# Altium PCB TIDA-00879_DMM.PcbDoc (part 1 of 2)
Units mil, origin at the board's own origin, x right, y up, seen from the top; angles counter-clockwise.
Board outline 2700 x 5000 mil, 4 copper layers (Layer 1 - Top Layer, Layer 2 - GND, Layer 3 - PWR, Layer 4 - Bottom Layer), stack 61.434 mil thick; 140 components, 132 nets, 483 pads, 130 vias.
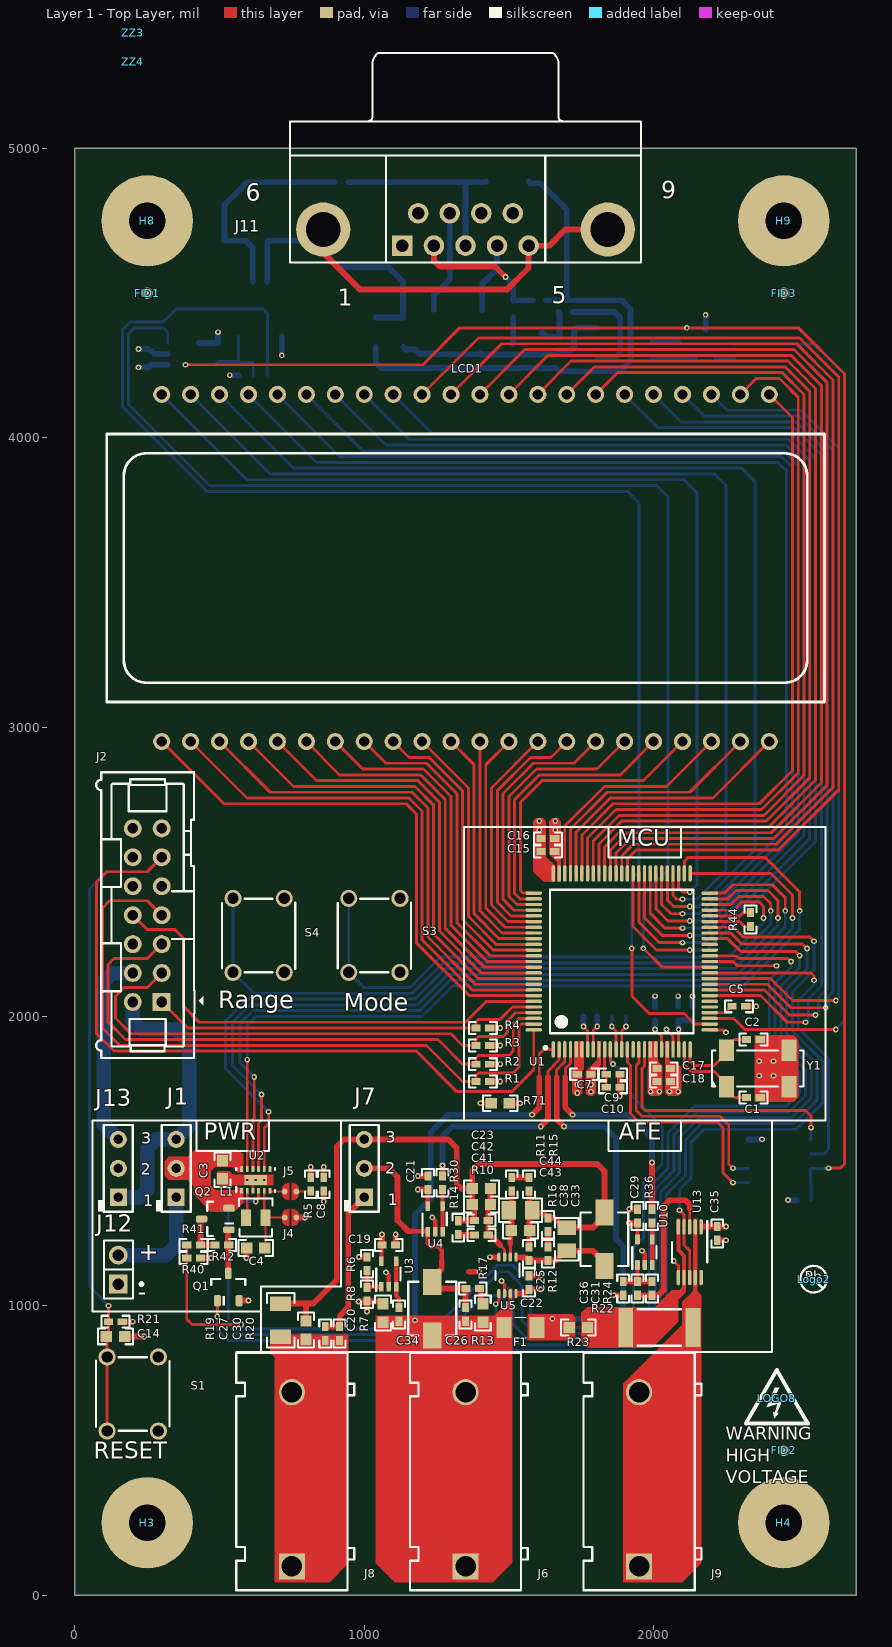
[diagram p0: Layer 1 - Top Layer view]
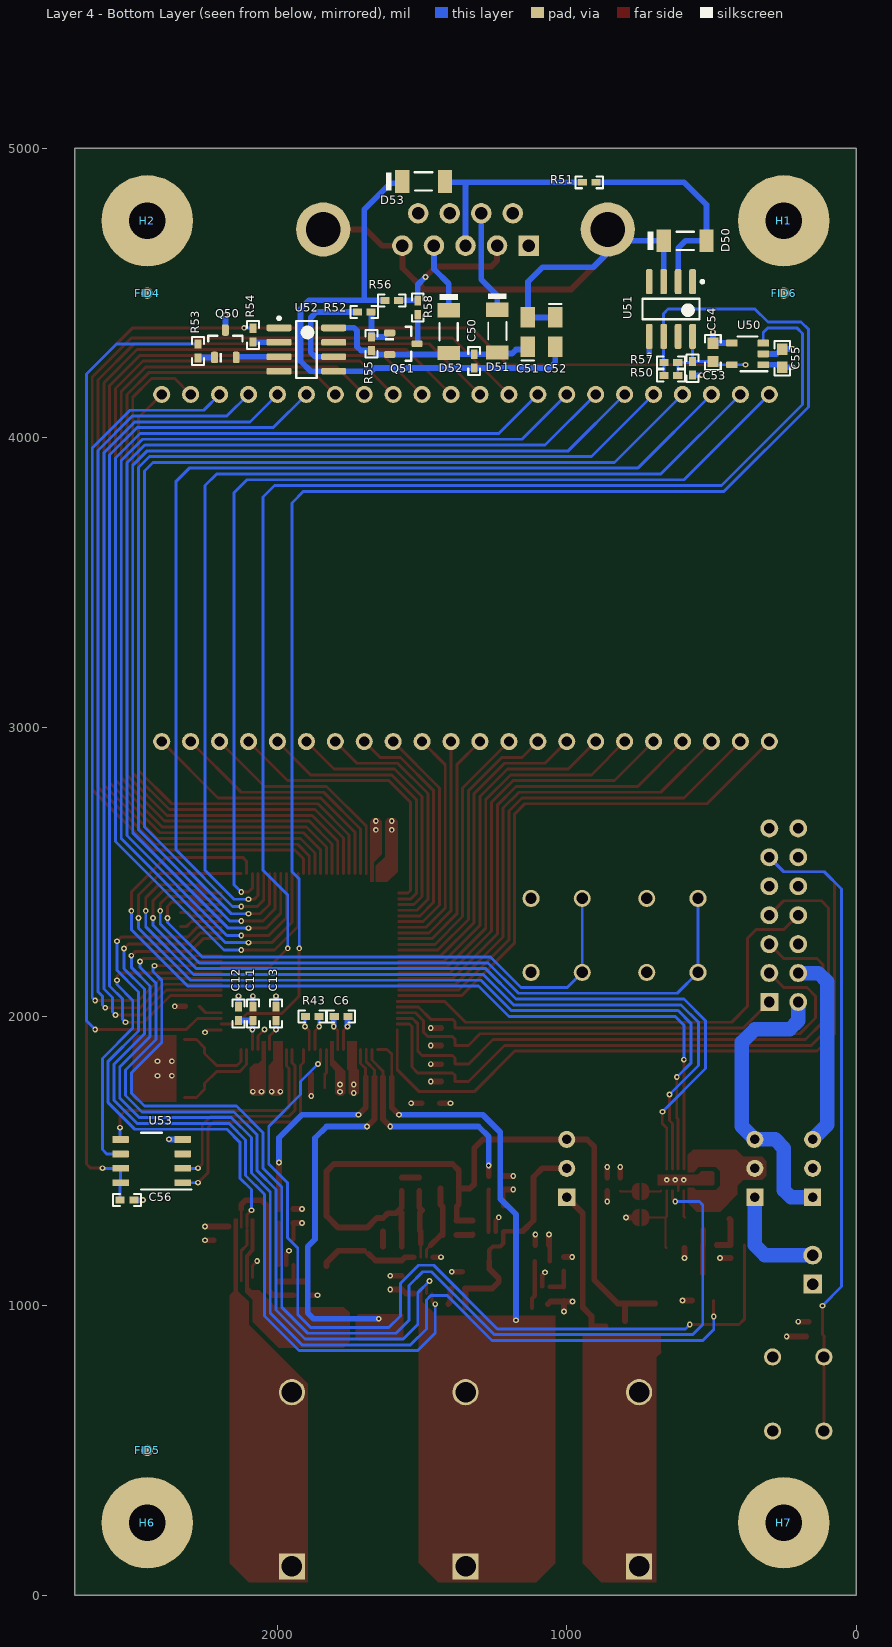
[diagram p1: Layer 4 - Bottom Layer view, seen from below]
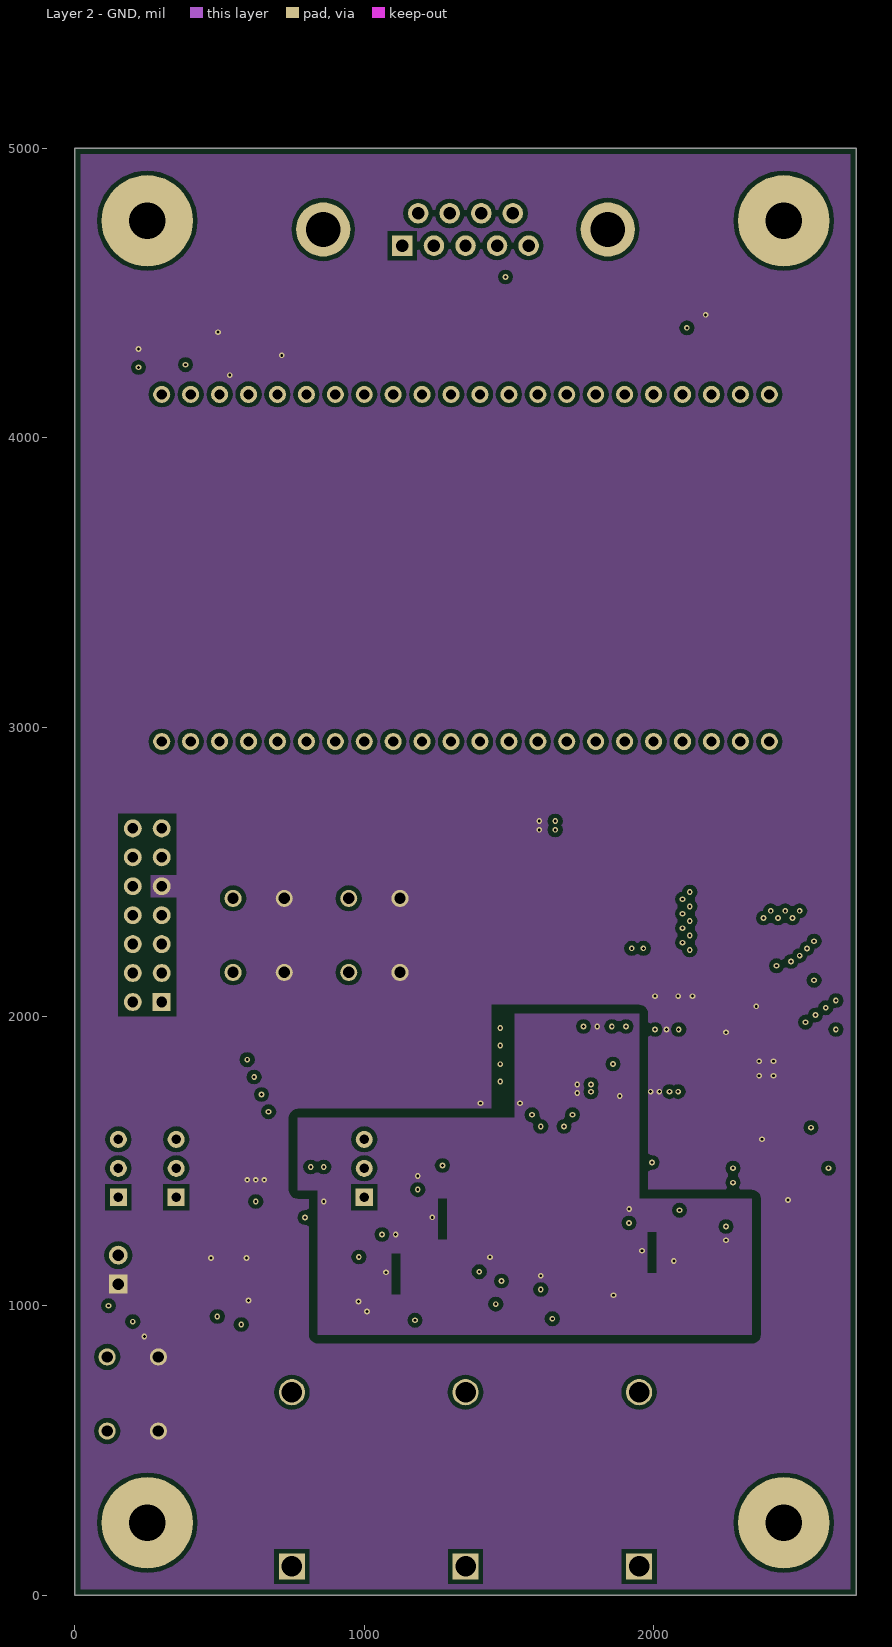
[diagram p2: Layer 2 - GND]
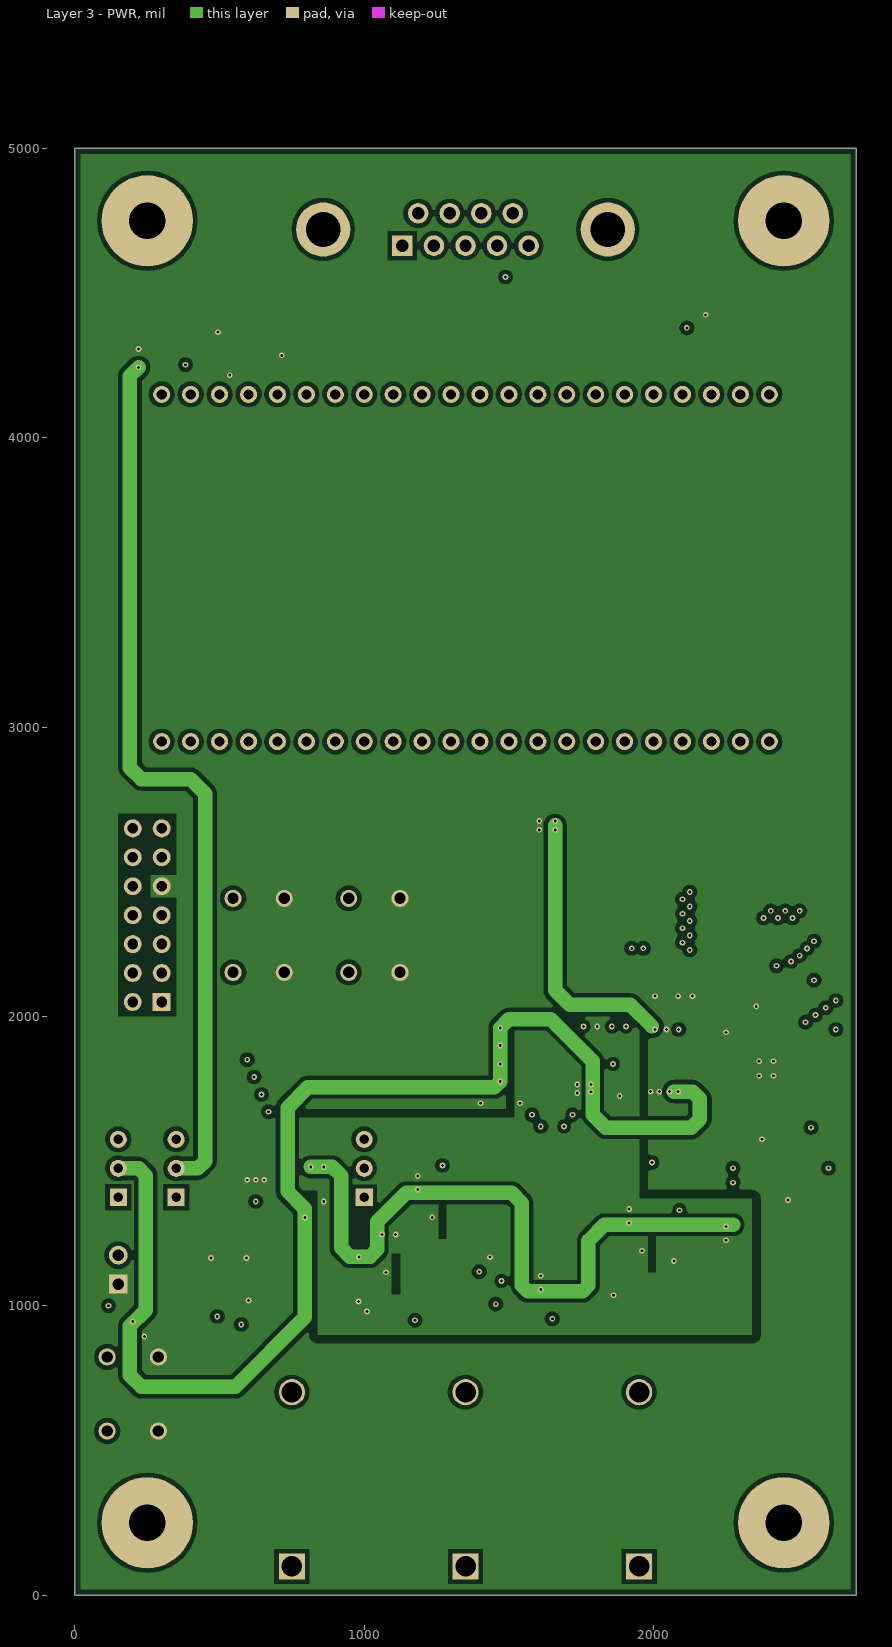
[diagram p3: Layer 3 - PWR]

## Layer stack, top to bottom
Top Solder: solder mask 0.4, Solder Resist, Dk 3.5
Layer 1 - Top Layer: signal copper 1.4
Dielectric 1: prepreg 18.6, 370HR, Dk 4.2
Layer 2 - GND: signal copper 1.417
Dielectric 2: core 18.6, 370HR, Dk 4.2
Layer 3 - PWR: signal copper 1.417
Dielectric 3: prepreg 18.6, 370HR, Dk 4.2
Layer 4 - Bottom Layer: signal copper 1.4
Bottom Solder: solder mask 0.4, Solder Resist, Dk 3.5

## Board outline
0,0 0,5000 2700,5000 2700,0

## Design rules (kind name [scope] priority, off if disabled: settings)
AcuteAngle [All] p1: minimum=4.50000000000000E+0001 checktracksonly=FALSE
AssemblyTestPointUsage [All] p1: valid=2
Clearance Clearance_Keepouts [((IsTrack Or IsArc) And Not InPoly) And IsFree and IsKeepOut vs ((IsTrack Or IsArc) And Not InPoly) And IsFree and IsKeepOut] p1: gap=0
Clearance Clearance_Poly [InPolygon] p2: gap=15 except(30: Poly-Poly)
Clearance [All] p3: gap=7
ComponentClearance ComponentClearance_MountingHoles_FiducialMarks [InComponentClass('Mounting Holes') vs InComponentClass('FiducialMark')] p1: gap=50 collisioncheckmode=3 verticalgap=10 showdistances=FALSE
ComponentClearance ComponentClearance_Shunt [InComponentClass('Header') vs InComponentClass('Shunt')] p2: gap=0 collisioncheckmode=3 verticalgap=0 showdistances=FALSE
ComponentClearance ComponentClearance_Logo [InComponentClass('Logo')] p3: gap=20 collisioncheckmode=3 verticalgap=10 showdistances=FALSE
ComponentClearance ComponentClearance_ScrewToNut [(HasFootprint('NY PMS 440 0025 PH')) vs (HasFootprint('Keystone_1902C'))] p4: gap=5 collisioncheckmode=3 verticalgap=10 showdistances=FALSE
ComponentClearance ComponentClearance_MountingHoles [InComponentClass('Mounting Holes')] p5: gap=25 collisioncheckmode=3 verticalgap=100000 showdistances=FALSE
ComponentClearance ComponentClearance_SmallPassives [HasFootprint('0201*') or HasFootprint('0402*') or HasFootprint('0508') or HasFootprint('0603*') or HasFootprint('0612') or HasFootprint('0805*') or HasFootprint('0815*') or HasFootprint('0830*') or HasFootprint('1206*') or HasFootprint('1210*') or HasFootprint('1808*') or HasFootprint('1812*') or HasFootprint('1825*') or HasFootprint('2010*') or HasFootprint('2220*') or HasFootprint('2225*') or HasFootprint('2512*') or HasFootprint('2728*') or HasFootprint('3518*') vs HasFootprint('0201*') or HasFootprint('0402*') or HasFootprint('0508') or HasFootprint('0603*') or HasFootprint('0612') or HasFootprint('0805*') or HasFootprint('0815*') or HasFootprint('0830*') or HasFootprint('1206*') or HasFootprint('1210*') or HasFootprint('1808*') or HasFootprint('1812*') or HasFootprint('1825*') or HasFootprint('2010*') or HasFootprint('2220*') or HasFootprint('2225*') or HasFootprint('2512*') or HasFootprint('2728*') or HasFootprint('3518*')] p6: gap=10 collisioncheckmode=3 verticalgap=10 showdistances=FALSE
ComponentClearance ComponentClearance_THtoSMT [IsThruComponent vs IsSMTComponent] p7: gap=10 collisioncheckmode=3 verticalgap=30 showdistances=FALSE
ComponentClearance ComponentClearance_THtoTH [IsThruComponent vs IsThruComponent] p8: gap=10 collisioncheckmode=3 verticalgap=10 showdistances=FALSE
ComponentClearance [All] p9: gap=10 collisioncheckmode=3 verticalgap=10 showdistances=FALSE
DiffPairsRouting [All] p1: maxlimit=100 minlimit=10 mostfreqgap=10 toplayer_minwidth=15 toplayer_maxwidth=15 toplayer_prefwidth=15 midlayer1_minwidth=15 midlayer1_maxwidth=15 midlayer1_prefwidth=15 midlayer2_minwidth=15 midlayer2_maxwidth=15 midlayer2_prefwidth=15 bottomlayer_minwidth=15 bottomlayer_maxwidth=15 bottomlayer_prefwidth=15 maxuncoupledlength=1000
FabricationTestPointUsage TestPointUsage [All] p1: valid=2 allowmultiple=FALSE
FabricationTestpoint Testpoint [All] p1: side=3 testpointundercomponent=TRUE minsize=40 maxsize=100 preferedsize=60 minholesize=0 maxholesize=40 preferedholesize=32 testpointgrid=1 allowsidetop=TRUE allowsidebottom=TRUE usegrid=TRUE gridtolerance=0.01
FanoutControl Fanout_LCC [IsLCC] p1: bgadir=Out bgaviamode=Centered fanoutstyle=Auto fanoutdirection=Alternating viagrid=1 // Fanout_LCC (Default Rule)
FanoutControl Fanout_BGA [IsBGA] p2: bgadir=Out bgaviamode=Centered fanoutstyle=Auto fanoutdirection=Alternating viagrid=1 // Fanout_BGA (Default Rule)
FanoutControl Fanout_Default [All] p4: bgadir=Out bgaviamode=Centered fanoutstyle=Auto fanoutdirection=Alternating viagrid=1 // Fanout_Default (Default Rule)
FanoutControl Fanout_Small [(CompPinCount < 5)] p5: bgadir=Out bgaviamode=Centered fanoutstyle=Auto fanoutdirection=OutThenIn viagrid=1 // Fanout_Small (Default Rule)
HoleSize [All] p1: absolutevalues=TRUE maxlimit=251 minlimit=7.87 maxpercent=80.000 minpercent=20.000
MinimumAnnularRing MinimumAnnularRing_ThermalPadVias [IsVia and InAnyComponent] p1: minimumring=5.91
MinimumAnnularRing [All] p2: minimumring=5
MinimumSolderMaskSliver MinimumSolderMaskSliver_Logo [InComponentClass('Logo') vs InComponentClass('Logo')] p1: minsoldermaskwidth=0.7
MinimumSolderMaskSliver [All] p2: minsoldermaskwidth=3.94
PlaneConnect [All] p1: planeconnectstyle=Relief reliefexpansion=10 reliefentries=4 reliefconductorwidth=10 reliefairgap=10
PolygonConnect [All] p1: connectstyle=Direct reliefconductorwidth=10 reliefentries=4 polygonreliefangle="90 Angle" airgapwidth=10
RoutingVias ThermalPadVias [IsVia and InAnyComponent] p1: holewidth=7.87 width=19.68 viastyle="Through Hole" minholewidth=7.87 minwidth=19.68 maxholewidth=12.99 maxwidth=23.62
RoutingVias [All] p2: holewidth=16 width=34 viastyle="Through Hole" minholewidth=7.87 minwidth=20 maxholewidth=40 maxwidth=65
SilkToBoardRegionClearance [Not ((IsComment or IsDesignator) And (Hide <> 'False')) and not InRegion(1000,500,4000,800)] p1:
SilkToSilkClearance SilkToSilkClearance_Pb-FreeLogo [(HasFootprint('Pb-Free_Overlay_Medium') OR HasFootprint('Pb-Free_Overlay_Small')) vs (HasFootprint('Pb-Free_Overlay_Medium') OR HasFootprint('Pb-Free_Overlay_Small'))] p1: silktosilkclearance=0
SilkToSilkClearance [All] p2: silktosilkclearance=4
SilkToSolderMaskClearance SilkToComponentPadClearance [IsPad and InAnycomponent] p1: minsilkscreentomaskgap=5 clearancetoexposedcopper=TRUE
SilkToSolderMaskClearance "Silk to Solder Mask Opening" [All] p2: minsilkscreentomaskgap=4 clearancetoexposedcopper=FALSE
SolderMaskExpansion [All] p1: expansion=1.97
Width [All] p1: maxlimit=100 minlimit=6 preferedwidth=10 checkconnectedcopper=TRUE
15 further rules are at their usual default settings.

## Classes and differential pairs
component class TIDA-00879_TEST: C50 C51 C52 C53 C54 C55 C56 D11 D50 D51 D52 D53 J11 Q50 Q51 R50 R51 R52 R53 R54 R55 R56 R57 R58 U50 U51 U52 U53
net class S[39..0]: S0 S1 S2 S3 S4 S5 S6 S7 S8 S9 S10 S11 S12 S13 S14 S15 S16 S17 S18 S19 S20 S21 S22 S23 S24 S25 S26 S27 S28 S29 S30 S31 S32 S33 S34 S35 S36 S37 S38 S39
component class TIDA-00879_MCU: C1 C2 C3 C4 C5 C6 C7 C8 C9 C10 C11 C12 C13 C14 C15 C16 C17 C18 J1 J2 J4 J5 J12 J13 L1 LCD LCD1 Q1 Q2 R1 R2 R3 R4 R5 R21 R40 R41 R42 R43 R44 R71 S1 S3 S4 U1 U2 Y1
component class "Mounting Holes": H3 H4 H8 H9
component class TIDA-00879_AFE: C19 C20 C21 C22 C23 C25 C26 C27 C29 C30 C31 C33 C34 C35 C36 C38 C41 C42 C43 C44 F1 J6 J7 J8 J9 LOGO8 R6 R7 R8 R10 R11 R12 R13 R14 R15 R16 R17 R19 R20 R22 R23 R24 R30 R36 U3 U4 U5 U10 U13
component class TIDA-00879_MISC: FID1 FID2 FID3 FID4 FID5 FID6 H1 H2 H3 H4 H6 H7 H8 H9 Logo2 ZZ2 ZZ3 ZZ4
component class FiducialMark: FID1 FID2 FID3 FID4 FID5 FID6
component class AssemblyNote: ZZ2 ZZ3 ZZ4
component class Header: J1 J2 J7 J12 J13
net class COM[3..0]: COM0 COM1 COM2 COM3

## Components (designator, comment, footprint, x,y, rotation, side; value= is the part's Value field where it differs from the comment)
C1 "GRM1555C1H180JA01D" 0402 2345,1720 r180 top
C2 "GRM1555C1H180JA01D" 0402 2345,1920 r0 top
C3 "GRM188R60J106ME84" 0603 510,1470 r270 top
C4 "GRM188R60J106ME84" 0603 625,1200 r180 top
C5 "C1005X5R1A475K050BC" 0402 2295,2035 r180 top
C6 "C1005X5R1A104K050BA" 0402 1780,2000 r0 bottom
C7 "C1005X5R1A104K050BA" 0402 1760,1800 r180 top
C8 "GRM155R60J226ME11D" 0402 860,1420 r90 top
C9 "C1005X5R1A104K050BA" 0402 1860,1800 r0 top
C10 "C1005X5R1A475K050BC" 0402 1860,1755 r180 top
C11 "C1005X5R1A104K050BA" 0402 2085,2010 r90 bottom
C12 "C1005X5R1A475K050BC" 0402 2135,2010 r90 bottom
C13 "C1005X5R1A104K050BA" 0402 2005,2010 r90 bottom
C14 "06033C104JAT2A" 0603 140.45,894.19 r0 top
C15 "C1005X5R1A104K050BA" 0402 1635,2570 r180 top
C16 "C1005X5R1A475K050BC" 0402 1635,2615 r0 top
C17 "C1005X5R1A104K050BA" 0402 2035,1820 r180 top
C18 "C1005X5R1A475K050BC" 0402 2035,1775 r0 top
C19 "C1005X5R1A104K050BA" 0402 1085,1210 r0 top
C20 "Used in BOM report" 0603 1065,975 r90 top
C21 "C1005X5R1A104K050BA" 0402 1220,1425 r90 top
C22 "C1005X5R1A104K050BA" 0402 1570,1080 r90 top
C23 "C0603C104J4RACTU" 0603 1405,1405 r0 top
C25 "GRM1555C1H511GA01D" 0402 1570,1180 r270 top
C26 "Used in BOM report" 0402 1350,970 r270 top
C27 "C1608C0G2A101F080AA" 0603 799,916 r90 top
C29 "C1005X5R1A104K050BA" 0402 1945,1310 r90 top
C30 "GRM1555C1H101FA01D" 0402 865,904.02 r90 top
C31 "Used in BOM report" 0402 1945,1060 r90 top
C33 "TZB4R200AB10B00" Murata_TZB4_A 1830,1230 r270 top
C34 "TZB4R200AB10B00" Murata_TZB4_A 1235,990 r270 top
C35 "C1005X5R1A104K050BA" 0402 2220,1250 r270 top
C36 "Used in BOM report" 0402 1895,1060 r90 top
C38 "08055A471FAT2A" 0805_HV 1700,1230 r270 top
C41 "GRM1557U1A182JA01D" 0402 1405,1295 r0 top
C42 "C1608C0G1E822J" 0603 1405,1350 r0 top
C43 "C0603C911J5GACTU" 0603 1540,1260 r180 top
C44 "C0805C103F1GACTU" 0805_HV 1540,1330 r180 top
C50 "C1005X5R1A104K050BA" 0402 1320,4265 r90 bottom
C51 "293D106X9050E2TE3" 3216-18 1135,4365 r90 bottom
C52 "293D106X9050E2TE3" 3216-18 1040,4365 r270 bottom
C53 "C1005X5R1A104K050BA" 0402 565,4240 r270 bottom
C54 "GRM188R61A105KA61D" 0603 495,4295 r90 bottom
C55 "GRM188R61A105KA61D" 0603 255,4275 r90 bottom
C56 "C1005X5R1A104K050BA" 0402 2520,1365 r180 bottom
D50 "LL103A-GS08" SOD-80 591,4681 r180 bottom
D51 "LL103A-GS08" SOD-80 1240,4369 r270 bottom
D52 "LL103A-GS08" SOD-80 1408,4367 r270 bottom
D53 "LL103A-GS08" SOD-80 1495,4886 r180 bottom
F1 "NANOSMDC020F-2" FUSE_NANO02 1540,925 r0 top
FID1 "Fiducial" Fiducial10-30#1 250,4500 r0 top
FID2 "Fiducial" Fiducial10-30#1 2450,500 r90 top
FID3 "Fiducial" Fiducial10-30#2 2450,4650 r0 top
FID4 "Fiducial" Fiducial10-30#1 2450,4500 r90 bottom
FID5 "Fiducial" Fiducial10-30#1 2450,500 r90 bottom
FID6 "Fiducial" Fiducial10-30#1 250,4500 r90 bottom
H1 "1902C" Keystone_1902C 250,4750 r180 bottom locked
H2 "1902C" Keystone_1902C 2450,4750 r180 bottom locked
H3 "NY PMS 440 0025 PH" "NY PMS 440 0025 PH" 250,250 r0 top locked
H4 "NY PMS 440 0025 PH" "NY PMS 440 0025 PH" 2450,250 r0 top locked
H6 "1902C" Keystone_1902C 2450,250 r180 bottom locked
H7 "1902C" Keystone_1902C 250,250 r180 bottom locked
H8 "NY PMS 440 0025 PH" "NY PMS 440 0025 PH" 250,4750 r0 top locked
H9 "NY PMS 440 0025 PH" "NY PMS 440 0025 PH" 2450,4750 r0 top locked
J1 "800-10-003-10-001000" Mill-Max_800-10-003-10-001000 350,1475 r90 top
J2 "N2514-6002-RB" 3M_x2514-60xx 250,2350 r90 top
J4 "Used in BOM report" JUMPER_SPCL 745,1305 r270 top
J5 "Used in BOM report" JUMPER_SPCL 745,1395 r270 top
J6 "571-0500" 571-0500 1350,400 r90 top
J7 "800-10-003-10-001000" Mill-Max_800-10-003-10-001000 1000,1475 r90 top
J8 "571-0100" 571-0100 750,400 r90 top
J9 "571-0200" 571-0200 1950,400 r90 top
J11 "182-009-213R171" NORCOMP_182-009-213R171 1350,5094 r0 top locked
J12 "90120-0122" CONN_90120-0122 150,1125 r90 top
J13 "800-10-003-10-001000" Mill-Max_800-10-003-10-001000 150,1475 r90 top
L1 "VLF302515MT-2R2M" VLF302515MT 625,1305 r0 top
LCD1 "FH-1152P" FH-1152P 1350,3550 r0 top locked
Logo2 "Pb-Free Symbol" Pb-Free_Overlay_Small 2553,1092 r0 top
LOGO8 "WARNING HIGH VOLTAGE" IEC_HighVoltage_Small 2426,681 r0 top
Q1 "BSS138" SOT-23 530,1065 r90 top
Q2 "FDN302P" SOT-23 485,1300 r180 top
Q50 "BC857B" SOT-23 2180,4325 r90 bottom
Q51 "BC857B" SOT-23 1565,4325 r180 bottom
R1 "CRCW040210K0JNED" 0402 1410,1775 r0 top
R2 "CRCW040210K0JNED" 0402 1410,1835 r0 top
R3 "CRCW040210K0JNED" 0402 1410,1900 r0 top
R4 "CRCW040210K0JNED" 0402 1410,1960 r0 top
R5 "CRCW040210R0JNED" 0402 815,1420 r90 top
R6 "CRCW0402100KFKED" 0402 1010,1145 r90 top
R7 "CRCW04024R70JNED" 0402 1120,970 r90 top
R8 "CRCW0402100KFKED" 0402 1010,1040 r90 top
R10 "CRCW04029K09FKED" 0402 1405,1245 r0 top
R11 "CRCW040290K9FKED" 0402 1510,1420 r270 top
R12 "CRCW04021M00FKED" 0402 1635,1180 r270 top
R13 "CRCW0603100MJPEAHR" 0603 1410,975 r270 top
R14 "CRCW040210R0FKED" 0402 1325,1270 r270 top
R15 "CRCW0402931RFKED" 0402 1570,1420 r90 top
R16 "CRCW040210K2FKED" 0402 1635,1280 r270 top
R17 "CRCW04020000Z0ED" 0402 1375,1060 r0 top
R19 "CRHV1206AF10M0FKE5" 1206 711,950 r90 top
R20 "CRCW0402499KFKED" 0402 915,904.02 r90 top
R21 "CRCW040247K0JNED" 0402 140,945 r0 top
R22 "CRCW251295R3FKEG" 2512 2020,925 r180 top
R23 "RL0603FR-070R5L" 0603 1740,925 r180 top
R24 "CRCW04020000Z0ED" 0402 1995,1060 r270 top
R30 "CRCW0402100RFKED" 0402 1270,1425 r270 top
R36 "CRCW0402100RFKED" 0402 1995,1310 r270 top
R40 "CRCW0402100KFKED" 0402 410,1165 r180 top
R41 "CRCW0402249KFKED" 0402 410,1210 r0 top
R42 "CRCW04021M00JNED" 0402 508,1210 r180 top
R43 "Used in BOM report" 0402 1880,2000 r180 bottom
R44 "Used in BOM report" 0402 2335,2335 r270 top
R50 "CRCW04022K20FKED" 0402 640,4215 r0 bottom
R51 "CRCW04021K00JNED" 0402 922,4883 r0 bottom
R52 "CRCW04021K00JNED" 0402 1700,4435 r180 bottom
R53 "CRCW04022K20JNED" 0402 2275,4300 r270 bottom
R54 "CRCW040268R0JNED" 0402 2085,4355 r270 bottom
R55 "CRCW040210K0JNED" 0402 1675,4325 r270 bottom
R56 "CRCW04021K50JNED" 0402 1605,4475 r180 bottom
R57 "CRCW04022K20FKED" 0402 640,4260 r180 bottom
R58 "CRCW0402220RJNED" 0402 1515,4450 r270 bottom
R71 "CRCW06030000Z0EA" 0603 1470,1700 r180 top
S1 "EVQ-PAD04M" SW_EVQ-PAD04M 200,695 r0 top
S3 "EVQ-PAD04M" SW_EVQ-PAD04M 1035,2280 r180 top
S4 "EVQ-PAD04M" SW_EVQ-PAD04M 635,2280 r180 top
U1 "MSP430F6736IPZ" PZ0100A_N 1890,2190 r90 top locked
U2 "TPS62740DSSR" DSS0012A 625,1435 r90 top
U3 "OPA333AIDCKT" DCK0005A_N 1085,1110 r90 top
U4 "OPA333AIDCKT" DCK0005A_N 1245,1300 r90 top
U5 "TS5A3359DCUR" DCU0008A_N 1495,1105 r270 top
U10 "OPA333AIDCKT" DCK0005A_N 1970,1185 r90 top
U13 "TS3A24159DGSR" DGS0010A_N 2125,1185 r270 top
U50 "TPS78230DDCR" DDC0005A_N 375,4290 r0 bottom
U51 "PS8802-1" SO-8 640,4445 r270 bottom
U52 "PS8802-1" SO-8 1900,4305 r180 bottom
U53 "23K640-I/SN" SOIC-8 2435,1500 r0 bottom
Y1 "MC-306 32.768K-E3:ROHS" XTAL_MC-306 2360,1820 r90 top
ZZ2 "These assemblies are ESD sensitive, ESD precautions shall be observed." AssemblyNote 200,5500 r0 top
ZZ3 "These assemblies must be clean and free from flux and all contaminants. Use of no clean flux is not acceptable." AssemblyNote 200,5400 r0 top
ZZ4 "These assemblies must comply with workmanship standards IPC-A-610 Class 2, unless otherwise specified." AssemblyNote 200,5300 r0 top

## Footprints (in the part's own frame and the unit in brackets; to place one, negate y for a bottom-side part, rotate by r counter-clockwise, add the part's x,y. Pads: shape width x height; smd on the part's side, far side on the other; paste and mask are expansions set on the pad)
3M_x2514-60xx [mil] "3M"
  rect 62x62 hole 37 paste+2: 1(-300,-50)
  round 62 hole 37: 2(-300,50) 3(-200,-50) 4(-200,50) 5(-100,-50) 6(-100,50) 7(0,-50) 8(0,50) 9(100,-50) 10(100,50) 11(200,-50) 12(200,50) 13(300,-50) 14(300,50)
  silkscreen extent -494,-193 494,177, body extent -494,-161 494,179, height 390
0402 [mm] "0402 from SM-752 data"
  rect 0.8x0.6 smd: 1(-0.6,0) 2(0.6,0)
  silkscreen extent -1.22,-0.52 1.22,0.52, body extent -0.55,-0.3 0.55,0.3, height 0.6
571-0100 [mm] "Deltron Emcon recommended land pattern 2003-10-13"
  rect 2.3x2.3 hole 1.8: 1(-7.65,0)
  round 2.3 hole 1.8: 2(7.65,0)
  silkscreen extent -9.74,-5.47 11.09,4.88, body extent -12.28,-5.48 11.09,4.88, height 12.41
571-0200 [mm] "Deltron Emcon recommended land pattern 2003-10-13"
  rect 2.3x2.3 hole 1.8: 1(-7.65,0)
  round 2.3 hole 1.8: 2(7.65,0)
  silkscreen extent -9.74,-5.47 11.09,4.88, body extent -12.28,-5.48 11.09,4.88, height 12.41
571-0500 [mm] "Deltron Emcon recommended land pattern 2003-10-13"
  rect 2.3x2.3 hole 1.8: 1(-7.65,0)
  round 2.3 hole 1.8: 2(7.65,0)
  silkscreen extent -9.74,-5.47 11.09,4.88, body extent -12.28,-5.48 11.09,4.88, height 12.41
0603 [mm] "0603 from SM-752 data"
  rect 1x0.95 smd: 1(-0.8,0) 2(0.8,0)
  silkscreen extent -1.52,-0.69 1.52,0.69, body extent -0.87,-0.47 0.87,0.47, height 1
0805_HV [mil] "0805 with 30mil clearance between pads"
  rect 50x63 smd: 1(-40,0) 2(40,0)
  silkscreen extent -74,-40 74,40, body extent -43,-29 43,29, height 57
1206 [mm] "1206 from SM-752 data"
  rect 1.3x1.85 smd: 1(-1.45,0) 2(1.45,0)
  silkscreen extent -2.4,-1.21 2.4,1.21, body extent -1.7,-0.9 1.7,0.9, height 1.35
2512 [mm] "Chip Resistor, Body 6.3x3.2mm, IPC Medium Density"
  rect 1.3x3.4 smd: 1(-2.95,0) 2(2.95,0)
  silkscreen extent -1.9,-1.6 1.9,1.6, body extent -3.22,-1.67 3.22,1.67, height 0.71
3216-18 [mm] "Medium density IPC, based on Kemet T495 dimensions"
  rect 1.8x1.25 smd: 1(-1.3,0) 2(1.3,0)
  silkscreen extent -2.49,-0.54 -2.49,0.54, body extent -1.7,-0.9 1.7,0.9, height 1.8
AssemblyNote [mil] "Assembly Note"
CONN_90120-0122 [mm] "Molex"
  rect 1.65x1.65 hole 1.016 mask+0: 1(-1.27,0)
  round 1.65 hole 1.016 mask+0: 2(1.27,0)
  silkscreen extent -2.54,-2.16 2.54,1.27, body extent -2.54,-1.27 2.54,1.27, height 9.29
DCK0005A_N [mm] "SOT353, 5-Leads, Body 2x1.3mm, Pitch 0.65mm, Lead Span 2.1mm, IPC Medium Density"
  rrect25% 0.85x0.4 smd: 1(-1.125,0.65) 2(-1.125,0) 3(-1.125,-0.65) 4(1.125,-0.65) 5(1.125,0.65)
  silkscreen extent -1.48,-1.02 0.55,1.1, body extent -1.14,-1 1.14,1, height 0.95
DCU0008A_N [mm] "TSSOP, 8-Leads, Body 2x2.3mm, Pitch 0.5mm, IPC Medium Density"
  oval 0.8x0.3 smd: 1(-1.6,0.75) 2(-1.6,0.25) 3(-1.6,-0.25) 4(-1.6,-0.75) 5(1.6,-0.75) 6(1.6,-0.25) 7(1.6,0.25) 8(1.6,0.75)
  silkscreen extent -1.05,-1.05 0.38,1.05, body extent -1.56,-1 1.56,1, height 0.9
DDC0005A_N [mm]
  rrect17% 1x0.6 smd: 1(-1.375,0.95) 2(-1.375,0) 3(-1.375,-0.95) 4(1.375,-0.95) 5(1.375,0.95)
  silkscreen extent -1.75,-1.52 0.88,1.53, body extent -1.41,-1.45 1.41,1.45, height 1.1
DGS0010A_N [mm] "TSSOP, 10-Leads, Body 3x3mm, Pitch 0.5mm, IPC Medium Density"
  oval 1.35x0.3 smd: 1(-2.225,1) 2(-2.225,0.5) 3(-2.225,0) 4(-2.225,-0.5) 5(-2.225,-1) 6(2.225,-1) 7(2.225,-0.5) 8(2.225,0) 9(2.225,0.5) 10(2.225,1)
  silkscreen extent -2.75,-1.55 0.9,1.55, body extent -2.45,-1.5 2.45,1.5, height 0.96
DSS0012A [mm] "SON, 12-Leads, Body 2x3mm, Pitch 0.5mm, Thermal Pad 2x0.9mm, TI Recommended"
  rrect40% 0.5x0.25 smd: 1(-0.95,1.25) 2(-0.95,0.75) 3(-0.95,0.25) 4(-0.95,-0.25) 5(-0.95,-0.75) 6(-0.95,-1.25) 7(0.95,-1.25) 8(0.95,-0.75) 9(0.95,-0.25) 10(0.95,0.25) 11(0.95,0.75) 12(0.95,1.25)
  rrect11% 0.9x2 smd paste-0.45: 13(0,0)
  Layer 1 - Top Layer region: -0.375,-1.5 -0.375,-1 -0.45,-1 -0.45,1 -0.375,1 -0.375,1.5 -0.125,1.5 -0.125,1 0.125,1 0.125,1.5 0.375,1.5 0.375,1 0.45,1 0.45,-1 0.375,-1 0.375,-1.5 0.125,-1.5 0.125,-1 -0.125,-1 -0.125,-1.5
  silkscreen extent -1.05,-1.7 1.05,1.7, body extent -1,-1.5 1,1.5, height 0.81
FH-1152P [mm]
  round 1.5 hole 0.9: 1(-26.67,-15.24) 2(-24.13,-15.24) 3(-21.59,-15.24) 4(-19.05,-15.24) 5(-16.51,-15.24) 6(-13.97,-15.24) 7(-11.43,-15.24) 8(-8.89,-15.24) 9(-6.35,-15.24) 10(-3.81,-15.24) 11(-1.27,-15.24) 12(1.27,-15.24) 13(3.81,-15.24) 14(6.35,-15.24) 15(8.89,-15.24) 16(11.43,-15.24) 17(13.97,-15.24) 18(16.51,-15.24) 19(19.05,-15.24) 20(21.59,-15.24) 21(24.13,-15.24) 22(26.67,-15.24) 23(26.67,15.24) 24(24.13,15.24) 25(21.59,15.24) 26(19.05,15.24) 27(16.51,15.24) 28(13.97,15.24) 29(11.43,15.24) 30(8.89,15.24) 31(6.35,15.24) 32(3.81,15.24) 33(1.27,15.24) 34(-1.27,15.24) 35(-3.81,15.24) 36(-6.35,15.24) 37(-8.89,15.24) 38(-11.43,15.24) 39(-13.97,15.24) 40(-16.51,15.24) 41(-19.05,15.24) 42(-21.59,15.24) 43(-24.13,15.24) 44(-26.67,15.24)
  silkscreen extent -31.5,-11.75 31.5,11.75
Fiducial10-30#1 [mm]
  round 1 smd mask+1: 1(0,0)
Fiducial10-30#2 [mm]
  round 1 smd mask+1: 1(0,-3.81)
FUSE_NANO02 [mm] "SMD, Body 3.2x1.585mm"
  rect 1.3x1.85 smd: 1(-1.45,0) 2(1.45,0)
  silkscreen extent -0.5,-0.9 0.5,0.9, body extent -1.7,-0.9 1.7,0.9, height 0.82
IEC_HighVoltage_Small [mil]
  silkscreen extent -107,-88 107,97
JUMPER_SPCL [mil]
  round 20 smd: 1(0,-20) 2(0,20)
  Layer 1 - Top Layer region: 30,5 26.65,17.5 17.5,26.65 5,30 0,30 0,5
  Layer 1 - Top Layer region: 0,5 0,30 -5,30 -17.5,26.65 -26.65,17.5 -30,5
  Layer 1 - Top Layer region: -30,-5 -26.65,-17.5 -17.5,-26.65 -5,-30 0,-30 0,-5
  Layer 1 - Top Layer region: 0,-5 0,-30 5,-30 17.5,-26.65 26.65,-17.5 30,-5
Keystone_1902C [mil] "Hex Standoff, 4-40 threaded, nylon"
  body extent -145,-126 146,126, height 501
Mill-Max_800-10-003-10-001000 [mm] "Mill-Max"
  rect 1.5x1.5 hole 0.85: 1(-2.54,0)
  round 1.5 hole 0.85: 2(0,0) 3(2.54,0)
  silkscreen extent -3.81,-1.27 3.81,1.78, body extent -3.81,-1.27 3.81,1.27, height 8.13
Murata_TZB4_A [mm] "SMD, 2-Leads, Body 4.5x4mm"
  rect 2.3x1.6 smd: 1(-2.35,0) 2(2.35,0)
  silkscreen extent -2.35,-2.1 2.35,2.1, body extent -2.35,-2.1 2.35,2.1, height 3.2
NORCOMP_182-009-213R171 [mm] "Connector; D Subminiature 9 Position; Right Angle"
  rect 1.8x1.8 hole 1.092: 1(-5.54,-10.92)
  round 1.8 hole 1.092: 2(-2.77,-10.92) 3(0,-10.92) 4(2.77,-10.92) 5(5.54,-10.92) 6(-4.155,-8.08) 7(-1.385,-8.08) 8(1.385,-8.08) 9(4.155,-8.08)
  round 4.76 hole 3.05: 10(-12.495,-9.5) 11(12.495,-9.5)
  silkscreen extent -15.4,-12.4 15.4,6, body extent -15.41,-12.98 15.41,6.1, height 12.55
"NY PMS 440 0025 PH" [mm] "4-40 nylon screw and mounting hole"
  round 8 hole 3.2: 1(0,0)
  body extent -3.3,-3.3 3.3,3.3, height 2.69
Pb-Free_Overlay_Small [mil]
  silkscreen extent -46,-46 46,46
PZ0100A_N [mm] "TSQFP, 100-Leads, Body 16.2x16.2mm (max), Pitch 0.50mm, IPC Medium Density"
  oval 1.45x0.3 smd: 1(-7.725,6) 2(-7.725,5.5) 3(-7.725,5) 4(-7.725,4.5) 5(-7.725,4) 6(-7.725,3.5) 7(-7.725,3) 8(-7.725,2.5) 9(-7.725,2) 10(-7.725,1.5) 11(-7.725,1) 12(-7.725,0.5) 13(-7.725,0) 14(-7.725,-0.5) 15(-7.725,-1) 16(-7.725,-1.5) 17(-7.725,-2) 18(-7.725,-2.5) 19(-7.725,-3) 20(-7.725,-3.5) 21(-7.725,-4) 22(-7.725,-4.5) 23(-7.725,-5) 24(-7.725,-5.5) 25(-7.725,-6) 51(7.725,-6) 52(7.725,-5.5) 53(7.725,-5) 54(7.725,-4.5) 55(7.725,-4) 56(7.725,-3.5) 57(7.725,-3) 58(7.725,-2.5) 59(7.725,-2) 60(7.725,-1.5) 61(7.725,-1) 62(7.725,-0.5) 63(7.725,0) 64(7.725,0.5) 65(7.725,1) 66(7.725,1.5) 67(7.725,2) 68(7.725,2.5) 69(7.725,3) 70(7.725,3.5) 71(7.725,4) 72(7.725,4.5) 73(7.725,5) 74(7.725,5.5) 75(7.725,6)
  oval 0.3x1.45 smd: 26(-6,-7.725) 27(-5.5,-7.725) 28(-5,-7.725) 29(-4.5,-7.725) 30(-4,-7.725) 31(-3.5,-7.725) 32(-3,-7.725) 33(-2.5,-7.725) 34(-2,-7.725) 35(-1.5,-7.725) 36(-1,-7.725) 37(-0.5,-7.725) 38(0,-7.725) 39(0.5,-7.725) 40(1,-7.725) 41(1.5,-7.725) 42(2,-7.725) 43(2.5,-7.725) 44(3,-7.725) 45(3.5,-7.725) 46(4,-7.725) 47(4.5,-7.725) 48(5,-7.725) 49(5.5,-7.725) 50(6,-7.725) 76(6,7.725) 77(5.5,7.725) 78(5,7.725) 79(4.5,7.725) 80(4,7.725) 81(3.5,7.725) 82(3,7.725) 83(2.5,7.725) 84(2,7.725) 85(1.5,7.725) 86(1,7.725) 87(0.5,7.725) 88(0,7.725) 89(-0.5,7.725) 90(-1,7.725) 91(-1.5,7.725) 92(-2,7.725) 93(-2.5,7.725) 94(-3,7.725) 95(-3.5,7.725) 96(-4,7.725) 97(-4.5,7.725) 98(-5,7.725) 99(-5.5,7.725) 100(-6,7.725)
  silkscreen extent -7.7,-6.3 6.3,6.82, body extent -8.01,-8.01 8.01,8.01, height 1.6
SO-8 [mm] "SOIC, 8-Leads, Body 5.0x4.0mm (max), Pitch 1.27mm, IPC Medium Density"
  rrect50% 2.2x0.6 smd: 1(-2.4,1.905) 2(-2.4,0.635) 3(-2.4,-0.635) 4(-2.4,-1.905) 5(2.4,-1.905) 6(2.4,-0.635) 7(2.4,0.635) 8(2.4,1.905)
  silkscreen extent -2.52,-2.5 0.9,2.88, body extent -3,-2.45 3,2.45, height 1.59
SOD-80 [mm] "VISHAY"
  rect 1.25x2 smd: 1(-1.875,0) 2(1.875,0)
  silkscreen extent -3.3,-0.8 0.76,0.8, body extent -1.85,-0.81 1.85,0.81, height 1.62
SOIC-8 [mm] "duplicate of SO-8.  SOIC, 8-Leads, Body 5.0x4.0mm (max), Pitch 1.27mm, IPC Medium Density"
  rrect17% 1.45x0.6 smd: 1(-2.725,1.905) 2(-2.725,0.635) 3(-2.725,-0.635) 4(-2.725,-1.905) 5(2.725,-1.905) 6(2.725,-0.635) 7(2.725,0.635) 8(2.725,1.905)
  silkscreen extent -3.5,-2.5 0.9,2.5, body extent -3,-2.45 3,2.45, height 1.63
SOT-23 [mm] "SOT23, 3-Leads, Body 2.9x1.3mm, Pitch 0.95mm, Lead Span 2.5mm, IPC Medium Density"
  rrect50% 1x0.6 smd: 1(-1.2,0.95) 2(-1.2,-0.95) 3(1.2,0)
  silkscreen extent -1.63,-1.5 0.7,1.5, body extent -1.16,-1.45 1.21,1.45, height 1
SW_EVQ-PAD04M [mm] "PANASONIC"
  round 1.5 hole 1: 1(-2.25,3.25) 2(-2.25,-3.25) 3(2.25,-3.25) 4(2.25,3.25)
  silkscreen extent -3.22,-3.22 3.22,3.22, body extent -3.15,-3.15 3.15,3.15, height 4.3
VLF302515MT [mm] "TDK"
  rect 0.9x1.45 smd: 1(-0.85,0) 2(0.85,0)
  silkscreen extent -1.45,-1.68 1.45,1.68, body extent -1.35,-1.6 1.35,1.6, height 1.5
XTAL_MC-306 [mm] "SEIKO-EPSON"
  rect 1.9x1.3 smd: 1(-1.6,2.75) 2(-1.6,-2.75) 3(1.6,-2.75) 4(1.6,2.75)
  silkscreen extent -1.6,-4 1.6,4, body extent -1.6,-4 1.6,4, height 2.55

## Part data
C1 C2: "CAP, CERM, 18 pF, 50 V, +/- 5%, C0G/NP0, 0402"
C3 C4: "CAP, CERM, 10 µF, 6.3 V, +/- 20%, X5R, 0603"
C5 C10 C12 C16 C18: "CAP, CERM, 4.7 µF, 10 V, +/- 10%, X5R, 0402"
C6 C7 C9 C11 C13 C15 C17 C19 C21 C22 C29 C35 C50 C53 C56: "CAP, CERM, 0.1 µF, 10 V, +/- 10%, X5R, 0402"
C8: "CAP, CERM, 22 µF, 6.3 V, +/- 20%, X5R, 0402"
C14: "CAP, CERM, 0.1 µF, 25 V, +/- 5%, X7R, 0603"
C20: library part Capacitor, "Cap, 0603 footprint placeholder"
C23: "CAP, CERM, 0.1 µF, 16 V, +/- 5%, X7R, 0603"
C25: "CAP, CERM, 510 pF, 50 V, +/- 2%, C0G/NP0, 0402"
C26 C31 C36: library part Capacitor, "Cap, 0402 footprint placeholder"
C27: "CAP, CERM, 100 pF, 100 V, +/- 1%, C0G/NP0, 0603"
C30: "CAP, CERM, 100 pF, 50 V, +/- 1%, C0G/NP0, 0402"
C33 C34: "Ceramic Trimmer Capacitor, 4.5 to 20 pF, SMT"
C38: "CAP, CERM, 470 pF, 50 V, +/- 1%, C0G/NP0, 0805"
C41: "CAP, CERM, 1800 pF, 10 V, +/- 5%, U2J, 0402"
C42: "CAP, CERM, 8200 pF, 25 V, +/- 5%, C0G/NP0, 0603"
C43: "CAP, CERM, 910 pF, 50 V, +/- 5%, C0G/NP0, 0603"
C44: "CAP, CERM, 0.01 µF, 100 V, +/- 1%, C0G/NP0, 0805"
C51 C52: "CAP, TANT, 10uF, 50V, +/-10%, 0.8 ohm, 7343-43 SMD"
C54 C55: "CAP, CERM, 1 µF, 10 V, +/- 10%, X5R, 0603"
D50 D51 D52 D53: "Diode, Schottky, 40 V, 0.2 A, DO-213AC"
F1: "Fuse, Resettable, 0.2 A, 24 VDC, SMD"
FID1 FID2 FID3 FID4 FID5 FID6: "Fiducial mark.  There is nothing to buy or mount."
H1 H2 H6 H7: "Standoff, Hex, 0.5\"L #4-40 Nylon"
H3 H4 H8 H9: "Machine Screw, Round, #4-40 x 1/4, Nylon, Philips panhead"
J1 J7 J13: "Header, 100mil, 3x1, TH"
J2: "Header (shrouded), 100mil, 7x2, Gold, TH"
J4 J5: library part Jumper_SPCL
J6: "Standard Banana Jack, insulated, 10A, red"
J8: "Standard Banana Jack, insulated, 10A, black"
J9: "Standard Banana Jack, insulated, 10A, blue"
J11: "CONN DB9 FEMALE R/A SOLDER TH"
J12: "Header, 100mil, 2x1, Tin, TH"
L1: "Inductor, Shielded, Ferrite, 2.2 µH, 1.57 A, 0.042 ohm, SMD"
LCD1: "160 segment LCD"
Logo2: library part Pb-Free
LOGO8: library part IEC_HighVoltage, "IEC 61010-1 High Voltage Warning"
Q1: "MOSFET, N-CH, 50 V, 0.22 A, SOT-23"
Q2: "MOSFET, P-CH, -20 V, -2.4 A, SOT-23"
Q50 Q51: library part "BC857C-7-F, Diodes Inc.", "Transistor, PNP, 45V, 0.1A, SOT-23"
R1 R2 R3 R4 R55: "RES, 10 k, 5%, 0.063 W, 0402"
R5: "RES, 10, 5%, 0.063 W, 0402"
R6 R8 R40: "RES, 100 k, 1%, 0.063 W, 0402"
R7: "RES, 4.7, 5%, 0.063 W, 0402"
R10: "RES, 9.09 k, 1%, 0.063 W, 0402"
R11: "RES, 90.9 k, 1%, 0.063 W, 0402"
R12: "RES, 1.00 M, 1%, 0.063 W, 0402"
R13: "RES, 100 M, 5%, 0.1 W, 0603"
R14: "RES, 10.0, 1%, 0.063 W, 0402"
R15: "RES, 931, 1%, 0.063 W, 0402"
R16: "RES, 10.2 k, 1%, 0.063 W, 0402"
R17 R24: "RES, 0, 5%, 0.063 W, 0402"
R19: "RES, 10.0 M, 1%, 0.3 W, 1206"
R20: "RES, 499 k, 1%, 0.063 W, 0402"
R21: "RES, 47 k, 5%, 0.063 W, 0402"
R22: "RES, 95.3, 1%, 1 W, 2512"
R23: "RES, 0.5, 1%, 0.1 W, 0603"
R30 R36: "RES, 100, 1%, 0.063 W, 0402"
R41: "RES, 249 k, 1%, 0.063 W, 0402"
R42: "RES, 1.0 M, 5%, 0.063 W, 0402"
R43 R44: library part Resistor, "RES, 0402 footprint placeholder"
R50 R57: "RES, 2.20 k, 1%, 0.063 W, 0402"
R51 R52: "RES, 1.0 k, 5%, 0.063 W, 0402"
R53: "RES, 2.2 k, 5%, 0.063 W, 0402"
R54: "RES, 68, 5%, 0.063 W, 0402"
R56: "RES, 1.5 k, 5%, 0.063 W, 0402"
R58: "RES, 220, 5%, 0.063 W, 0402"
R71: "RES, 0, 5%, 0.1 W, 0603"
S1 S3 S4: "SWITCH TACTILE SPST-NO 0.02A 15V, TH"
U1: "25 MHz Mixed Signal Microcontroller with 128 KB Flash, 8192 B SRAM and 72 GPIOs, -40 to 85 degC, 100-pin QFP (PZ), Green (RoHS & no Sb/Br)"
U2: "360nA IQ Step Down Converter for Low Power Applications, DSS0012A"
U3 U4 U10: "17 uA, MicroPower, Precision, Zero Drift CMOS Operational Amplifier, 1.8 to 5.5 V, -40 to 125 degC, 5-pin SOT23 (DCK0005A), Green (RoHS & no Sb/Br)"
U5: "1-Ohm SP3T ANALOG SWITCH 5-V/3.3-V SINGLE-CHANNEL 3:1 MULTIPLEXER/DEMULTIPLEXER, DCU0008A"
U13: "0.3-Ohm DUAL SPDT ANALOG SWITCH DUAL-CHANNEL 2:1 MULTIPLEXER/DEMULTIPLEXER, DGS0010A"
U50: "Single Output LDO, 150 mA, Fixed 3 V Output, 2.2 to 5.5 V Input, with 0.5 uA Quiescent Current, 5-pin SOT (DDC), -40 to 125 degC, Green (RoHS & no Sb/Br)"
U53: "64K SPI Bus Low-Power Serial SRAM, SOIC-8"
Y1: "Crystal, 32.768kHz, 6pF, SMD"
ZZ2 ZZ3 ZZ4: library part AssemblyNote

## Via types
v1: diameter 20, hole 10, Layer 1 - Top Layer to Layer 4 - Bottom Layer, tented both sides, 127 vias
v2: diameter 19.68, hole 7.87, Layer 1 - Top Layer to Layer 4 - Bottom Layer, 3 vias

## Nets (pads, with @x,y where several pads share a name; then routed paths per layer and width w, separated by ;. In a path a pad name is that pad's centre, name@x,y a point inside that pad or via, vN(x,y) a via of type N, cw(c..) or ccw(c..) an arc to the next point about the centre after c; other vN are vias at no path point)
AGND: C6.2 C7.2 C8.1 C9.2 C10.1 C19.2 C20.2 C21.2 C22.2 C29.2 C35.2 C36.1 R8.1 R71.1 U1.5 U1.6 U1.8 U3.2 U4.2 U5.4 U10.2 U13.6 | length 849.2
  Layer 1 - Top Layer w10: U1.8@1791.57,1885.87 1791.57,1951.57 v1@1805,1965 ; v1(2070,1155) 2085.63,1139.37 U13.6@2085.63,1097.4
  Layer 1 - Top Layer w15: v1(1075.01,1115.59) 1085.01,1105.59 U3.2@1085.01,1066.3 ; v1(1235.01,1305.59) 1245.01,1295.59 U4.2@1245.01,1256.3 ; v1(1960,1190) 1970,1180 U10.2@1970,1140.71
  Layer 1 - Top Layer w20: v1(860,1360) C8.1@860,1396.38 ; v1(980,1015) 1008.62,1015 R8.1@1010,1016.38 ; v1(1010,980) R8.1@1010,1016.38 ; C20.2@1065,1006.5 1056.5,1015 1011.38,1015 R8.1@1010,1016.38 ; C19.2@1108.62,1210 v1(1108.62,1246.38) ; v1(1185,1448.62) C21.2@1220,1448.62 ; v1(1435,1167.99) U5.4@1461,1167.99 ; R71.1@1501.5,1700 v1(1537.87,1700) ; C22.2@1570,1103.62 v1(1610,1103.62) ; v1(1861.38,1036.38) C36.1@1895,1036.38 ; v1@1883.62,1725 C10.1@1883.62,1755 C9.2@1883.62,1800 ; v1(1915.59,1334.21) C29.2@1945.59,1334.21 ; C35.2@2220,1226.38 v1(2250,1226.38)
  Layer 4 - Bottom Layer w20: C6.2@1803.62,2000 1805.47,1998.15 v1(1805.47,1965.47)
  other v1: 1883.15,1725.47 1736.38,1735 1736.38,1765
AVCC: C8.2 C19.1 C21.1 C22.1 C29.1 C35.1 R5.2 R6.2 U3.5 U4.5 U5.8 U10.5 U13.1 | length 2917.4
  Layer 1 - Top Layer w15: U3.5@1059.41,1154.29 1059.41,1208.03 C19.1@1061.38,1210 ; U4.5@1219.41,1344.29 1219.41,1400.79 C21.1@1220,1401.38 ; U10.5@1944.41,1229.29 1944.41,1285.79 C29.1@1945,1286.38
  Layer 1 - Top Layer w20: R5.2@815,1443.62 v1(815,1480) ; C8.2@860,1443.62 v1(860,1480) ; v1(981.38,1168.62) R6.2@1010,1168.62 ; C19.1@1061.38,1210 v1(1061.38,1246.38) ; v1(1185,1401.38) C21.1@1220,1401.38 ; U5.8@1529,1042.01 1555.63,1042.01 C22.1@1570,1056.38 v1(1610,1056.38) ; v1(1915,1286.38) C29.1@1945,1286.38 ; U13.1@2169,1273.62 C35.1@2220,1273.62 v1(2250,1273.62)
  Layer 3 - PWR w50: v1(815,1480) v1(860,1480) 890,1480 920,1450 920,1200 950,1170 1020,1170 1045,1195 1045,1290 1145,1390 1510,1390 1545,1355 1545,1070 1565,1050 1755,1050 1775,1070 1775,1225 1830,1280 2275,1280
COM0: LCD1.28 U1.32 | length 3118.7
  Layer 1 - Top Layer w10: U1.32@2194.13,2071.89 2370,2071.89 2461.89,1980 v1(2525,1980)
  Layer 4 - Bottom Layer w10: LCD1.28@1900,4150 2015,4035 2485,4035 2580,3940 2580,2105 2535,2060 2535,1990 v1(2525,1980)
COM1: LCD1.27 U1.33 | length 3045.1
  Layer 1 - Top Layer w10: U1.33@2194.13,2091.57 2383.43,2091.57 2470,2005 v1(2560,2005)
  Layer 4 - Bottom Layer w10: LCD1.27@2000,4150 2095,4055 2493.28,4055 2600,3948.28 2600,2095 2570,2065 2570,2015 v1(2560,2005)
COM2: LCD1.26 U1.34 | length 2971.6
  Layer 1 - Top Layer w10: U1.34@2194.13,2111.26 2393.74,2111.26 2475,2030 v1(2595,2030)
  Layer 4 - Bottom Layer w10: LCD1.26@2100,4150 2175,4075 2501.57,4075 2620,3956.57 2620,2085 2605,2070 2605,2040 v1(2595,2030)
COM3: LCD1.25 U1.35 | length 2898
  Layer 1 - Top Layer w10: U1.35@2194.13,2130.94 2404.06,2130.94 2480,2055 v1(2630,2055)
  Layer 4 - Bottom Layer w10: LCD1.25@2200,4150 2255,4095 2509.85,4095 2640,3964.85 2640,2065 v1(2630,2055)
CS: U1.14 U53.1 | length 823.7
  Layer 1 - Top Layer w10: U1.14@1909.68,1885.87 1909.68,1840.32 1920,1830 1920,1665 1950,1635 2220,1635 2240,1615 2240,1460 v1(2274.53,1425.47) v1@2275,1425
  Layer 4 - Bottom Layer w10: v1(2274.53,1425.47) 2275,1425 U53.1@2327.72,1425
DGND: C1.1 C2.2 C3.2 C4.2 C5.1 C11.2 C12.2 C13.2 C14.2 C15.2 C16.1 C17.2 C18.1 C53.2 C54.2 C55.2 C56.2 J2.9 J12.1 Q1.2 Q50.3 R40.1 R71.2 S1.3 S1.4 S3.1 S3.2 S4.1 S4.2 U1.18 U1.19 U1.22 U1.26 U1.75 U2.3 U2.13 U50.2 U50.4 U51.5 U53.4 Y1.2 Y1.3 | length 960.2
  Layer 1 - Top Layer w8: U2.3@615.16,1397.6 615.16,1425.16 v2(625,1435)
  Layer 1 - Top Layer w10: v1(2044.37,1955) 2067.17,1932.2 U1.22@2067.17,1885.87 ; U1.26@2194.13,1953.78 2241.22,1953.78 v1(2250,1945)
  Layer 1 - Top Layer w20: C14.2@171.95,894.19 v1(240,894.19) ; R40.1@433.62,1165 v1(470,1165) ; Q1.2@567.4,1017.76 v1(600,1017.76) ; v1(593.5,1165) C4.2@593.5,1200 ; v1(1402.13,1700) R71.2@1438.5,1700 ; C5.1@2318.62,2035 v1(2355,2035)
  Layer 4 - Bottom Layer w20: v1(220,4306.5) C55.2@255,4306.5 ; C55.2@265,4300 275,4290 U50.2@320.87,4290 ; U50.4@429.13,4327.4 494.09,4327.4 C54.2@495,4326.5 v1(495,4365) ; v1(535,4216.38) C53.2@565,4216.38 ; v1(715,4285) U51.5@715,4350.51 ; C13.2@2005,2033.62 v1(2005,2070) ; C11.2@2085,2033.62 v1(2085,2070) ; C12.2@2135,2033.62 v1(2135,2070) ; Q50.3@2180,4372.24 v1(2180,4425) ; U53.4@2327.72,1575 v1@2375,1575 ; v1@2465,1365 C56.2@2496.38,1365
  other v1: 2464.53,1365.47 2374.53,1575.47 1990,1740 2020,1740 2365,1795 2415,1795 2365,1845 2415,1845 1605,2645 1605,2675
  other v2: 595.47,1435 654.53,1435
DVCC: C7.1 C17.1 C18.2 J4.2 J13.2 R1.2 R2.2 R3.2 R4.2 R21.2 U1.9 U1.21 | length 4607
  Layer 1 - Top Layer w20: R21.2@163.63,945 v1(200,945) ; J4.2@765,1305 v1(795,1305) ; R1.2@1433.62,1775 v1(1470,1775) ; R2.2@1433.62,1835 v1(1470,1835) ; R3.2@1433.62,1900 v1(1470,1900) ; R4.2@1433.62,1960 v1(1470,1960)
  Layer 3 - PWR w50: J13.2@150,1475 220,1475 245,1450 245,985 190,930 190,760 230,720 555,720 795,960 v1(795,1305) 795,1335 735,1395 735,1685 805,1755 1450,1755 v1(1470,1775) v1(1470,1960) 1500,1990 1645,1990 1790,1845 1790,1660 1835,1615 2130,1615 2160,1645 2160,1715 2135,1740 v1(2085,1740) 2070,1740
  other v1: 1783.62,1739.51 2055,1740 1783.62,1765
DVSYS: C13.1 C15.1 C16.2 U1.20 U1.74 | length 1066
  Layer 1 - Top Layer w10: v1(2005,1955) 2027.8,1932.2 U1.20@2027.8,1885.87
  Layer 3 - PWR w50: 1660,2660 v1(1660,2645) 1660,2090 1710,2040 1920,2040 1994.5,1965.5
  Layer 4 - Bottom Layer w20: v1(2005,1955) C13.1@2005,1986.38
  other v1: 1660,2675
I+: F1.2 R23.2 U1.3 | length 1353.1
  Layer 1 - Top Layer w10: 1665,1790 1665,1815.28 1693.15,1843.43 U1.3@1693.15,1885.87
  Layer 1 - Top Layer w20: 1665,1790 1665,1645 v1(1690,1620)
  Layer 4 - Bottom Layer w20: v1(1650,955) 1875,955 1895,975 1895,1205 1870,1230 1870,1580 1830,1620 v1(1690,1620)
I-: R36.1 U1.4 | length 797.5
  Layer 1 - Top Layer w10: 1695,1790 1695,1820 1712.83,1837.83 U1.4@1712.83,1885.87
  Layer 1 - Top Layer w20: 1695,1790 1695,1685 v1(1720,1660) ; R36.1@1995,1333.62 v1@1995,1495
  Layer 4 - Bottom Layer w20: v1(1720,1660) 1915,1660 1994.53,1580.47 v1(1994.53,1495.47)
IRANGE_SEL: U1.44 U13.4 U13.8 | length 2023.9
  Layer 1 - Top Layer w10: v1(2090,1330) 2105.32,1314.68 U13.4@2105.32,1272.6 ; U13.4@2105.32,1262.6 2105.32,1209.68 2125,1190 U13.8@2125,1097.4 U13.8@2125,1087.4 ; U1.44@2194.13,2308.11 2276.89,2308.11 2310,2275 2540,2275 v1(2555,2260)
  Layer 4 - Bottom Layer w10: v1(2090,1330) 2090,1401.86 2130,1441.86 2130,1565.15 2174.85,1610 2493.14,1610 2585,1701.86 2585,1845 2480,1950 2480,2084.72 2555,2159.72 v1(2555,2260)
NetC1_2: C1.2 U1.24 Y1.1 | length 317.2
  Layer 1 - Top Layer w10: U1.24@2106.54,1885.87 2106.54,1833.46 2130,1810 2210,1810 2251.73,1768.27 Y1.1@2251.73,1757.01 ; Y1.1@2251.73,1748.27 2280,1720 C1.2@2321.38,1720
NetC2_1: C2.1 U1.25 Y1.4 | length 291.9
  Layer 1 - Top Layer w10: U1.25@2126.22,1885.87 2126.22,1843.78 2140,1830 2210,1830 2251.73,1871.73 Y1.4@2251.73,1882.99 2251.73,1891.73 2280,1920 C2.1@2321.38,1920
NetC4_1: C4.1 J4.1 L1.2 U2.5 | length 266.6
  Layer 1 - Top Layer w8: U2.5@654.53,1397.6 654.53,1308.94 L1.2@658.46,1305 ; C4.1@656.5,1200 658.46,1201.97 L1.2@658.46,1305 ; J4.1@725,1305 L1.2@658.46,1305
NetC5_2: C5.2 U1.29 | length 86.4
  Layer 1 - Top Layer w10: U1.29@2194.13,2012.83 2247.83,2012.83 2270,2035 C5.2@2271.38,2035
NetC23_1: C23.1 C25.1 C27.2 C33.1 C38.1 C41.1 C42.1 C43.1 C44.1 J7.3 R14.1 R15.1 R16.1 R19.2 | length 2745.6
  Layer 1 - Top Layer w20: R19.2@694,1007.59 798,1007.59 ; C27.2@799,947.5 799,1006.59 798,1007.59 ; R14.1@1325,1293.62 1326.38,1295 C41.1@1381.38,1295 1380,1296.38 1380,1343.5 C42.1@1373.5,1350 C23.1@1373.5,1405 ; C25.1@1570,1203.62 1570,1258.5 C43.1@1571.5,1260 1571.5,1321.5 C44.1@1580,1330 ; R15.1@1570,1396.38 1570,1340 C44.1@1580,1330 ; 798,1007.59 823.59,1007.59 905,1089 905,1550 930,1575 J7.3@1000,1575 1290,1575 1320,1545 1320,1420 1335,1405 C23.1@1373.5,1405 ; C23.1@1373.5,1405 1373.5,1468.5 1395,1490 1805,1490 1830,1465 C33.1@1830,1322.52 1830,1310 1790,1270 C38.1@1700,1270 1690,1270 1656.38,1303.62 R16.1@1635,1303.62 1618.62,1320 1590,1320 C44.1@1580,1330
NetC23_2: C23.2 C41.2 C42.2 R10.2 U5.3 | length 267.4
  Layer 1 - Top Layer w10: 1470,1210 1485.16,1194.84 U5.3@1485.16,1167.99
  Layer 1 - Top Layer w20: C23.2@1436.5,1405 C42.2@1436.5,1350 1428.62,1342.13 C41.2@1428.62,1295 R10.2@1428.62,1245 1435,1245 1470,1210
NetC25_2: C25.2 C33.2 C38.2 R12.2 U5.1 | length 328.7
  Layer 1 - Top Layer w20: U5.1@1530,1167.99 1558.39,1167.99 C25.2@1570,1156.38 R12.2@1635,1156.38 1661.38,1156.38 C38.2@1685,1180 ; C38.2@1700,1190 1790,1190 1830,1150 C33.2@1830,1137.48
NetC26_1: C26.1 C34.1 J7.2 R17.1 U4.1 | length 812.2
  Layer 1 - Top Layer w15: 1162.24,1257.6 1217.52,1257.6 U4.1@1219.41,1255.71 1219.41,1215.59 1230,1205 1255,1205 1267.76,1192.24 1267.76,1155
  Layer 1 - Top Layer w20: J7.2@1000,1475 1085,1475 1115,1445 1115,1295 1152.4,1257.6 1162.24,1257.6 ; 1267.76,1155 1267.76,1127.76 1235,1095 C34.1@1235,1082.52 1257.52,1060 R17.1@1351.38,1060 1350,1058.62 C26.1@1350,993.62
NetC27_1: C27.1 C30.1 J8.1 J8.2 R19.1 R20.1
NetC30_2: C30.2 J7.1 R20.2 | length 531.6
  Layer 1 - Top Layer w20: C30.2@865,928.62 915,928.62 915,965 945,995 945,1320 J7.1@1000,1375
NetC31_1: C31.1 R24.2 U13.3 | length 569.6
  Layer 1 - Top Layer w10: U13.3@2125,1272.6 2125,1335
  Layer 1 - Top Layer w20: C31.1@1945,1036.38 R24.2@1995,1036.38 2016.38,1036.38 2035,1055 2035,1345 2055,1365 2110,1365 2125,1350 2125,1335
NetC31_2: C31.2 C36.2 R24.1 U10.1 | length 157.3
  Layer 1 - Top Layer w15: U10.1@1944.41,1140.71 1944.41,1084.21 C31.2@1945,1083.62
  Layer 1 - Top Layer w20: C36.2@1895,1083.62 C31.2@1945,1083.62 R24.1@1995,1083.62
NetC43_2: C43.2 C44.2 R11.2 U5.2 | length 237.6
  Layer 1 - Top Layer w10: U5.2@1504.84,1167.99 1504.84,1214.84
  Layer 1 - Top Layer w20: 1504.84,1214.84 1504.84,1256.34 C43.2@1508.5,1260 1508.5,1321.5 C44.2@1500,1330 1510,1340 R11.2@1510,1396.38
NetC50_1: C50.1 C52.2 D53.1 R56.1 U52.5 | length 1929.9
  Layer 4 - Bottom Layer w20: C52.2@1040,4313.82 1040,4260 1058.62,4241.38 C50.1@1320,4241.38 1663.62,4241.38 1675,4230 U52.5@1805.51,4230 1885,4230 1920,4265 1920,4445 1890,4475 1700,4475 ; D53.1@1568.82,4886 1574.82,4880 1609,4880 1700,4789 1700,4475 ; R56.1@1628.62,4475 1700,4475
NetC50_2: C50.2 C51.1 D51.2 D52.2 Q51.2 R55.2 U52.8 | length 754
  Layer 4 - Bottom Layer w20: C51.1@1135,4313.82 1143.82,4305 1175,4305 1188.82,4291.18 1240,4291.18 1242.56,4288.62 C50.2@1320,4288.62 1397.44,4288.62 1400,4291.18 1403.58,4287.6 Q51.2@1612.24,4287.6 1661.22,4287.6 R55.2@1675,4301.38 1711.38,4301.38 1725,4315 1725,4370 1735,4380 U52.8@1805.51,4380
NetC51_2: C51.2 C52.1 D50.1 J11.5 J11.10 J11.11 U51.3 | length 2215.3
  Layer 1 - Top Layer w10: J11.11@1841.93,4719.98 J11.11@1842.13,4719.79
  Layer 1 - Top Layer w20: J11.10@858.07,4719.98 858.07,4639.67 984.74,4513 1494,4513 1568.11,4587.11 J11.5@1568.11,4664.08 1639.08,4664.08 1694.98,4719.98 J11.11@1841.93,4719.98
  Layer 4 - Bottom Layer w20: U51.3@665,4539.49 665,4680.82 D50.1@664.82,4681 819.09,4681 J11.10@858.07,4719.98 858.07,4639.67 908.37,4589.37 1084.25,4589.37 1134.25,4539.37 1134.25,4416.93 C51.2@1135,4416.18 C52.1@1040,4416.18
NetD50_2: D50.2 R51.1 U51.2 | length 762.3
  Layer 4 - Bottom Layer w20: U51.2@615,4539.49 615,4656 590,4681 D50.2@517.18,4681 517.18,4805.18 595,4883 R51.1@898.38,4883
NetD51_1: D51.1 J11.7 | length 356
  Layer 4 - Bottom Layer w20: D51.1@1240,4442.82 1240,4492 1295.47,4547.47 J11.7@1295.47,4775.89
NetD52_1: D52.1 J11.4 | length 244.4
  Layer 4 - Bottom Layer w20: D52.1@1408,4440.82 1408,4532 1459.05,4583.06 J11.4@1459.05,4664.08
NetD53_2: D53.2 J11.3 R51.2 | length 694.4
  Layer 4 - Bottom Layer w20: R51.2@945.62,4883 1418.18,4883 D53.2@1421.18,4886 ; 1346,4880 1350,4876 J11.3@1350,4664.08
NetJ1_1: J1.1 J12.2 | length 379.5
  Layer 4 - Bottom Layer w50: J12.2@150,1175 315,1175 350,1210 J1.1@350,1375
NetJ2_4: J2.4 J13.3 | length 678.1
  Layer 4 - Bottom Layer w50: J13.3@150,1575 100,1625 100,2120 130,2150 J2.4@200,2150
NetJ5_1: J5.1 U2.6 | length 51.9
  Layer 1 - Top Layer w8: U2.6@674.21,1397.6 676.81,1395 J5.1@725,1395
NetJ5_2: J5.2 R5.1 | length 50.6
  Layer 1 - Top Layer w8: J5.2@765,1395 813.62,1395 R5.1@815,1396.38
NetJ9_1: J9.1 J9.2 R22.1 U13.2 U13.9
NetJ11_2: J11.2 R56.2 R58.1 | length 482.8
  Layer 1 - Top Layer w20: J11.2@1240.94,4664.08 1240.94,4612.06 1261,4592 1452,4592 v1(1488,4556)
  Layer 4 - Bottom Layer w20: v1(1488,4556) 1515,4529 R58.1@1515,4473.62 1516.38,4475 R56.2@1581.38,4475
NetL1_1: L1.1 U2.2 | length 94.2
  Layer 1 - Top Layer w8: L1.1@591.54,1305 595.47,1308.94 U2.2@595.47,1397.6
NetQ1_1: Q1.1 U1.42 | length 3930.1
  Layer 1 - Top Layer w10: v1@492.6,962.4 Q1.1@492.6,1017.76 ; U1.42@2194.13,2268.74 2256.26,2268.74 2300,2225 2490,2225 v1(2505,2210)
  Layer 4 - Bottom Layer w10: v1(492.13,962.87) 492.13,917.87 530,880 1258.19,880 1413.19,1035 1470,1035 1485,1020 1485,920 1540,865 1915,865 2025,975 2025,1393.43 2090,1458.43 2090,1581.72 2158.28,1650 2476.57,1650 2545,1718.43 2545,1825 2440,1930 2440,2105 2505,2170 v1(2505,2210)
NetQ1_3: Q1.3 Q2.1 R42.1 | length 150.9
  Layer 1 - Top Layer w20: Q2.1@528.62,1262.6 528.62,1210 530,1208.62 Q1.3@530,1112.24
NetQ2_3: Q2.3 R41.2 R42.2 | length 139.5
  Layer 1 - Top Layer w20: Q2.3@437.76,1300 433.62,1295.87 R41.2@433.62,1210 R42.2@481.38,1210
NetQ50_1: Q50.1 R53.2 | length 58.2
  Layer 4 - Bottom Layer w20: Q50.1@2217.4,4277.76 2273.62,4277.76 R53.2@2275,4276.38
NetQ50_2: Q50.2 U52.3 | length 149
  Layer 4 - Bottom Layer w20: U52.3@1994.49,4280 2140.35,4280 Q50.2@2142.6,4277.76
NetQ51_1: Q51.1 R52.2 R55.1 | length 156.3
  Layer 4 - Bottom Layer w20: Q51.1@1612.24,4362.4 1617.6,4362.4 1631.38,4348.62 R55.1@1675,4348.62 1675,4431.38 R52.2@1671.38,4435
NetQ51_3: Q51.3 R58.2 | length 92.3
  Layer 4 - Bottom Layer w20: Q51.3@1512.76,4325 1515,4327.24 R58.2@1515,4416.38
NetR6_1: R6.1 R8.2 U3.1 | length 108
  Layer 1 - Top Layer w15: R6.1@1010,1121.38 R8.2@1010,1063.62 1012.09,1065.71 U3.1@1059.41,1065.71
